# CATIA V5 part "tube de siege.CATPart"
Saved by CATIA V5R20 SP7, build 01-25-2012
Part number: tube de siege
Bounding box of the stored display mesh (mm): x 464.976 to 523.821, y -23 to 23, z 203.383 to 394.023
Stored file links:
  D:\thinkmotion-MPB\Dropbox\Pack 1 sylvain\CFAO_2010_yyang\yyang\CFAO_2010_yyang\tube de siege.CATPart
  D:\thinkmotion-MPB\Dropbox\Pack 1 sylvain\CFAO_2010_yyang\yyang\CFAO_2010_yyang\yyang.CATProduct
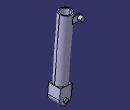
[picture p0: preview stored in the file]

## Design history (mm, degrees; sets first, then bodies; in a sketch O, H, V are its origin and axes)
External parameters (linked from other documents)
  `External.demi_distance entre les oreilles` = 15 mm
  `External.hauteur du cube` = 40 mm
  `External.distance entre pivot en bas et le fond` = 10 mm
  `External.rayon du trou des liaisons` = 5 mm
  `External.demi_largeur de l'oreille` = 7.5 mm
  `External.demi_distance entre pivots en haut` = 11 mm
  `External.epaisseur du pivot en haut` = 3 mm
  `External.hauteur du tube` = 150 mm
  `External.rayon du tube` = 12 mm
  `External.epaisseur de l'oreille` = 3 mm
  `External.demi-distance entre les des pivot` = 9 mm
  `External.epaisseur du pivot` = 2 mm
Set1
  Plane1: linked copy from another document
  Point1: linked copy from another document
  Plane2: linked copy from another document
  Point2: linked copy from another document
  Line1: linked copy from another document
  Line2: linked copy from another document
Body1 (main body)
  Sketch1 on Plane1, origin (1.5041, 0, 170.6336), H (0.9965, 0, 0.0839), V (0, 1, 0)
    line L1 (494.5355, 15) -> (524.5355, 15)
    line L2 (524.5355, 15) -> (524.5355, -15)
    line L3 (524.5355, -15) -> (494.5355, -15)
    line L4 (494.5355, -15) -> (494.5355, 15)
    reference projected point E1 (509.5355, 0) from Point1
    reference projected point E2 (509.5355, 0) from Point1
    reference projected point E3 (509.5355, 0) from Point1
    reference projected point E4 (509.5355, 0) from Point1
    distance L2 E1 = 15 {= `External.demi_distance entre les oreilles`}
    distance L1 E2 = 15 {= `External.demi_distance entre les oreilles`}
    distance L4 E3 = 15 {= `External.demi_distance entre les oreilles`}
    distance L3 E4 = 15 {= `External.demi_distance entre les oreilles`}
    horizontal: L1 H, L3 H
    vertical: L2 V, L4 V
  Pad1: profile Sketch1, direction (-0.0839, 0, 0.9965), length 30 {= `External.hauteur du cube`-`External.distance entre pivot en bas et le fond`}, opposite side length 10 {= `External.distance entre pivot en bas et le fond`}
  Sketch2 on Plane2, origin (0, 0, 0), H (-1, 0, 0), V (0, 0, 1)
    line L1 (-494.7638, 385.2904) -> (-471.845, 383.36)
    line L2 (-494.7638, 385.2904) -> (-496.0228, 370.3433)
    line L3 (-496.0228, 370.3433) -> (-473.104, 368.4129)
    arc A1 centre (-472.4745, 375.8865) radius 7.5 from (-473.104, 368.4129) to (-471.845, 383.36) ccw
    point P3 (-472.4745, 375.8865)
    reference projected point E1 (-472.4745, 375.8865) from Point2
    reference projected point E2 (-472.4745, 375.8865) from Point2
    reference projected line E3 (-509.5386, 209.876) -> (-495.6901, 374.2938) from Line1
    reference projected line E4 (-473.802, 375.9983) -> (-496.7209, 377.9287) from Line2
    reference projected line E5 (-473.802, 375.9983) -> (-496.7209, 377.9287) from Line2
    distance A1 E2 = 7.5 {= `External.demi_largeur de l'oreille`}
    coincidence: P3 E1, L2 E3
    tangency: L1 A1, L3 A1
    parallelism: L3 E4, L1 E5
  Pad2: profile Sketch2, direction (0, 1, 0), length 14 {= `External.demi_distance entre pivots en haut`+`External.epaisseur du pivot en haut`}, mirrored extent
  Sketch3 on Plane2, origin (0, 0, 0), H (-1, 0, 0), V (0, 0, 1)
    line L1 (-494.7638, 385.2904) -> (-464.3715, 382.7305)
    line L2 (-464.3715, 382.7305) -> (-465.6304, 367.7835)
    line L3 (-465.6304, 367.7835) -> (-496.0228, 370.3433)
    line L4 (-496.0228, 370.3433) -> (-494.7638, 385.2904)
    reference projected arc E1 centre (-472.4745, 375.8865) radius 7.5 from (-472.4745, 368.3865) to (-472.4745, 383.3865) ccw from edge [face of Pad2 from Sketch2.A1 | end face of Pad2]
    reference projected line E2 (-487.757, 384.7002) -> (-510.6758, 386.6306) from edge [face of Pad2 from Sketch2.L1 | end face of Pad2]
    reference projected line E3 (-510.678, 371.5777) -> (-487.7592, 369.6473) from edge [face of Pad2 from Sketch2.L3 | end face of Pad2]
    reference projected line E4 (-509.5386, 209.876) -> (-495.6901, 374.2938) from Line1
    reference projected line E5 (-473.802, 375.9983) -> (-496.7209, 377.9287) from Line2
    tangency: L2 E1
    coincidence: L1 E2, E3 L3, L4 E4
    perpendicularity: E5 L2
  Pocket1: profile Sketch3, direction (0, -1, 0), length 11 {= `External.demi_distance entre pivots en haut`}, mirrored extent
  Sketch4 on end face of Pad1, origin (1.4997, 0, 200.7395), H (0.9965, 0, 0.0839), V (0, 1, 0)
    circle A1 centre (507.0131, 0) radius 15
    point P1 (507.0131, 0)
    point P2 (548.8604, 0)
    reference projected point E1 (507.0131, 0) from Point1
    reference projected point E2 (507.0131, 0) from Point1
    distance A1 E2 = 15 {= `External.demi_distance entre les oreilles`}
    coincidence: P1 E1
  Pad3: profile Sketch4, direction (-0.0839, 0, 0.9965), length 150 {= `External.hauteur du tube`}
  Sketch5 on end face of Pad1, origin (1.4997, 0, 200.7395), H (0.9965, 0, 0.0839), V (0, 1, 0)
    circle A1 centre (507.0131, 0) radius 12
    point P1 (507.0131, 0)
    reference projected point E1 (507.0131, 0) from Point1
    reference projected point E2 (507.0131, 0) from Point1
    distance A1 E2 = 12 {= `External.rayon du tube`}
    coincidence: P1 E1
  Pocket2: profile Sketch5, direction (-0.0839, 0, 0.9965), length 150 {= `External.hauteur du tube`}
  Fillet1: radius 15 {= `External.demi_distance entre les oreilles`}, on edge [start face of Pad1 | face of Pad1 from Sketch1.L4]; edge [start face of Pad1 | face of Pad1 from Sketch1.L2]
  Sketch6 on face of Pad1 from Sketch1.L3, origin (0, -15, 0), H (1, 0, 0), V (0, 0, 1)
    circle A1 centre (509.2418, 213.3991) radius 5
    point P1 (509.2418, 213.3991)
    reference projected point E1 (509.2418, 213.3991) from Point1
    reference projected point E2 (509.2418, 213.3991) from Point1
    distance A1 E2 = 5 {= `External.rayon du trou des liaisons`}
    coincidence: P1 E1
  Pad4: profile Sketch6, direction (0, -1, 0), length 3 {= `External.epaisseur de l'oreille`}
  Mirror1: of Pad4, about Plane2
  Sketch7 on start face of Pad2, origin (0, -14, 0), H (1, 0, 0), V (0, 0, 1)
    circle A1 centre (472.4745, 375.8865) radius 5
    point P1 (472.4745, 375.8865)
    reference projected point E1 (472.4745, 375.8865) from Point2
    reference projected point E2 (472.4745, 375.8865) from Point2
    distance A1 E2 = 5 {= `External.rayon du trou des liaisons`}
    coincidence: P1 E1
  Pad5: profile Sketch7, direction (0, -1, 0), length 9 {= 23mm-`External.epaisseur du pivot en haut`-`External.demi_distance entre pivots en haut`}
  Mirror2: of Pad5, about Plane2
